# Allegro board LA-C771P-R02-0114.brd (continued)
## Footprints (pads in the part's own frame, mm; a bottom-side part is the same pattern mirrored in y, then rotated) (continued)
W25Q64DWSSIG_SO8
  oval 0.635x1.676 smd: 1(0,0) 2(1.27,0) 3(2.54,0) 4(3.81,0) 5(3.81,7.25) 6(2.54,7.25) 7(1.27,7.25) 8(0,7.25)
Y_7V25000014_4P
  rect 1.397x1.194 smd: 1(0,0) 2(2.2,0) 3(2.2,1.7) 4(0,1.7)
Y_CRG3201212_4P
  rect 1.397x1.194 smd: 1(0,0) 2(2.2,0) 3(2.2,1.6) 4(0,1.6)
Y_Q13FC135000040_2P
  rect 0.991x1.803 smd: 1(0,0) 2(2.5,0)
Y_X3G025000DC1H_4P
  rect 1.397x1.194 smd: 1(0,0) 2(2.2,0) 3(2.2,1.7) 4(0,1.7)
YSLC05CH_SOT23-3
  oval 1.016x1.524 smd: 1(0,0) 2(0.965,2.083) 3(-0.965,2.083)
Z32H320TC-LPC-T28-233_TSSOP28
  oval 0.381x1.626 smd: 1(0,0) 2(0.65,0) 3(1.3,0) 4(1.95,0) 5(2.6,0) 6(3.25,0) 7(3.9,0) 8(4.55,0) 9(5.2,0) 10(5.85,0) 11(6.5,0) 12(7.15,0) 13(7.8,0) 14(8.45,0) 15(8.45,5.8) 16(7.8,5.8) 17(7.15,5.8) 18(6.5,5.8) 19(5.85,5.8) 20(5.2,5.8) 21(4.55,5.8) 22(3.9,5.8) 23(3.25,5.8) 24(2.6,5.8) 25(1.95,5.8) 26(1.3,5.8) 27(0.65,5.8) 28(0,5.8)

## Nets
1.05VS_GATE: CQ20.1 Q5.1 RQ9.1 UQ3.4
1.8VS_ON: CQ12.2 RQ3.1 UQ2.3
1.35VS_ON: CQ15.2 RQ4.1 UQ2.5
3V5V_EN: PC313.1 PR306.2 PR307.2 PR308.1 PU301.1 PU302.1
3V/5VALW_PG: PR314.2 PR501.2 PR601.1 PU301.2 UB1.15
3V_FB: PC302.1 PU301.3
3V_SN: PC312.1 PR305.2
3V_VIN: PC301.1 PC303.1 PC305.1 PC306.1 PL301.2 PU301.8
3VS_ON: CQ4.1 RQ1.1 UQ1.3
5V_FB: PC317.1 PU302.3
5V_SN: PC326.1 PR311.2
5V_VIN: PC314.1 PC315.1 PC316.1 PC319.1 PL303.2 PR312.1 PU302.8
5VS_ON: CQ7.2 RQ2.2 UQ1.5
+0.675VS: CD16.1 CD17.1 CD18.1 JDIMM1.203 JDIMM1.204 PJ403.2 RQ6.1
+0.675VS_R: Q3.1 RQ6.2
+0.675VSP: PC406.1 PC407.1 PJ403.1 PU303.2 PU303.20
+1.05VALW: CC50.2 CC51.2 CC52.2 CC53.2 CC55.2 CC93.1 CQ17.2 PJ501.2 PR123.1 UC4.B6 UC4.C3 UC4.C5 UC4.U22 UC4.V18 UC4.V22 UC4.Y19 UQ3.5 UQ3.6 UQ3.7 UQ3.8
+1.05VALWP: PC503.1 PC504.1 PC505.1 PC506.1 PC507.1 PJ501.1 PL403.2 PR505.1
+1.05VS: CC54.1 CC56.1 CC57.1 CC58.1 CC59.2 CC60.2 CC62.2 CC63.2 CC64.2 CC65.2 CC66.2 CC68.2 CC72.2 CC73.2 CC75.2 CC76.2 CC77.2 CC78.2 CC80.2 CC82.2 CC84.2 CC85.2 CC86.2 CC87.2 CC88.2 CC90.2 CC92.2 CQ18.2 CQ19.2 PR122.1 RB23.2 RC20.2 RC39.1 RC74.1 RC75.2 RQ7.2 UC4.AA33 UC4.AA36 UC4.AD35 UC4.AF16 UC4.AF18 UC4.AF21 UC4.AF33 UC4.AF35 UC4.AF36 UC4.AG21 UC4.AG33 UC4.AG35 UC4.AJ18 UC4.AJ36 UC4.AK18 UC4.AK19 UC4.AK21 UC4.AK35 UC4.AK36 UC4.AM16 UC4.AM18 UC4.AM21 UC4.AN18 UC4.AN19 UC4.AN21 UC4.AN25 UC4.AN29 UC4.AN30 UC4.G1 UC4.M14 UC4.U18 UC4.U19 UC4.U33 UC4.U35 UC4.V24 UC4.V32 UC4.V33 UC4.Y18 UC4.Y22 UC4.Y24 UC4.Y35 UC4.Y36 UQ3.1 UQ3.2 UQ3.3
+1.05VS_R: Q4.1 RQ7.1
+1.05VS_SOC: RC75.1 UC4.AC32 UC4.Y32
+1.05VSP_ON: PC501.1 PR501.1 PR503.1 PU501.7
+1.8VALW: CC22.1 CC61.1 CQ9.2 CW4.1 PJ602.2 QC2.2 QC3.2 RB7.2 RB13.1 RC26.1 RC28.2 RC29.2 RC35.1 RC36.2 RC38.1 RC45.1 RC46.1 RC50.1 RC51.1 RC52.1 RC59.1 RC61.1 RC81.2 RM19.2 RPC5.5 RPC5.6 RPC5.7 RPC5.8 RPC6.3 RPC6.4 RW5.1 RW8.1 UC4.AA18 UC4.N20 UC4.U24 UC4.U25 UC4.V25 UC10.8 UQ2.1 UQ2.2 UW2.1
+1.8VALWP: PC604.1 PC605.1 PJ602.1 PR603.1 PU601.3 PU601.4
+1.8VS: CC67.1 CC69.1 CC70.1 CC71.1 CC74.1 CY12.1 PJ5.2 QC4.2 QC5.2 QY2.2 QY3.2 RA2.2 RA5.2 RC9.2 RC14.1 RC17.1 RC21.1 RC22.1 RC58.1 RC79.2 RC82.2 RPC3.5 RPC3.6 RPC3.7 RPC3.8 RPC9.5 RPC9.6 RPC9.7 RPY1.3 RPY1.4 RX3.1 RY2.1 UC4.AM30 UC4.AM32 UC4.AN32 UC4.U38 UC5.5 UC6.5 UC7.5 UC8.5
+1.8VS_AVDD2: CA9.1 RA5.1 UA1.40
+1.8VS_OUT: CQ11.2 PJ5.1 UQ2.13 UQ2.14
+1.35V: CC31.2 CC32.2 CD4.1 CD5.1 CD6.1 CD7.1 CD8.1 CD9.1 CD10.1 CD11.1 CD12.1 CD13.1 CD14.1 CD15.1 CQ16.2 JDIMM1.75 JDIMM1.76 JDIMM1.81 JDIMM1.82 JDIMM1.87 JDIMM1.88 JDIMM1.93 JDIMM1.94 JDIMM1.99 JDIMM1.100 JDIMM1.105 JDIMM1.106 JDIMM1.111 JDIMM1.112 JDIMM1.117 JDIMM1.118 JDIMM1.123 JDIMM1.124 PJ1.2 PJ2.2 PJ401.2 PJ402.2 RC6.1 RD1.1 RD3.1 UQ2.6 UQ2.7
+1.35V_SOC: CC33.2 CC34.2 CC35.2 CC36.2 CC37.1 CC38.1 PJ1.1 PJ2.1 RC69.2 UC4.A48 UC4.AK38 UC4.AM38 UC4.AV41 UC4.AV42 UC4.BB46 UC4.BD49 UC4.BD52 UC4.BD53 UC4.BF44 UC4.BG51 UC4.BJ48 UC4.C51 UC4.D44 UC4.F49 UC4.F52 UC4.F53 UC4.H46 UC4.M41 UC4.M42 UC4.V38 UC4.Y38
+1.35VP: PC409.1 PC410.1 PC411.1 PC412.1 PC413.1 PC414.1 PJ401.1 PJ402.1 PL402.1 PR406.1 PR407.2 PU303.5 PU303.19
+1.35VS: CC40.1 CC41.1 CC42.1 CC43.1 CC44.1 CC45.1 CC46.1 CC47.1 CC48.1 CC49.1 PJ6.2 RC43.1 RC70.2 UC4.AA25 UC4.AD36 UC4.AF19 UC4.AG18 UC4.AG19 UC4.AG32 UC4.AJ19 UC4.U36 UC4.V36
+1.35VS_OUT: CQ13.2 PJ6.1 UQ2.8 UQ2.9
+3V_HDD: CO13.1 JHDD1.8 JHDD1.9 JHDD1.10 RO2.2
+3V_HUB: CS9.1 RS12.1 RS13.1 RS14.1 US2.20
+3V_LAN: CL7.1 CL8.1 CL9.1 CL10.1 RL1.2 RL4.2 UL1.11 UL1.23 UL1.32
+3VALW: C2.1 C12.1 CL1.2 CQ1.2 D3.3 JP1.1 JPWRB1.5 PJ301.2 PJ502.1 PJ601.1 PR105.2 PR502.1 PR712.1 PR729.2 RB2.1 RB27.1 RC27.2 RC76.2 RL1.1 UC9.5 UQ1.1 UQ1.2
+3VALW_EC: CB3.1 CB4.1 CB5.1 CB6.1 L3.1 RB2.2 RB4.2 RB5.2 RB10.2 RB18.1 RB20.2 RB21.2 RPB1.1 RPB1.2 RW3.1 UB1.22 UB1.33 UB1.96
+3VALW_SOC: CC79.1 CC81.1 CC83.1 RC76.1 UC4.N18 UC4.N22 UC4.P18
+3VALWP: PC307.1 PC308.1 PC309.1 PC310.1 PJ301.1 PL302.2 PR302.2 PU301.4
+3VDD_CODEC: CA1.1 CA2.1 CA18.2 RA1.2 UA1.1 UA1.36
+3VLP: CB7.1 PC311.1 PR107.2 PR115.2 PR222.2 PR314.1 PU301.5 R3.2 R7.2 R16.2 RB4.1 RB6.2 RB11.1 UA1.20 UB1.111
+3VS: CD19.1 CR5.2 CR6.2 CX2.1 CX10.2 JDIMM1.199 JEDP1.16 PJ3.2 PR602.1 QX2.3 QY1.5 R1.1 RA1.1 RA15.2 RB14.2 RB15.2 RC25.1 RC68.2 RC77.2 RC78.2 RL2.1 RM1.1 RO2.1 RPB1.3 RPB1.4 RPC1.2 RPC1.3 RPC1.4 RR8.2 RW1.2 RW4.1 UR1.9 UX1.5
+3VS_1.8VS_SOC: RC78.1 RC79.1 UC4.AM27
+3VS_CMOS: CX12.1 JEDP1.1 RX10.2
+3VS_OUT: CQ3.2 PJ3.1 UQ1.13 UQ1.14
+3VS_R_CMOS: CX11.1 QX2.1 RX10.1
+3VS_SOC: CC89.1 CC91.1 RC77.1 UC4.AN24 UC4.AN27
+3VS_TCM: CW1.1 CW2.1 CW3.1 RW1.1 UW1.10 UW1.19 UW1.24 UW1.28
+3VS_WLAN: CM1.1 JWLAN1.2 JWLAN1.24 JWLAN1.39 JWLAN1.41 JWLAN1.52 RM1.2 RM18.2 RM20.2
+5V_HUB: CS7.1 CS8.1 RS10.1 RS15.2 US2.19
+5V_ODD: CO9.1 JODD1.9 JODD1.10 RO1.2
+5VALW: CQ8.2 CS3.2 CS10.1 CS13.2 PC601.1 PJ302.2 PR404.1 PR405.1 PR718.2 PR719.1 PR722.1 PU601.6 RQ5.2 RQ9.2 RS15.1 UQ1.4 UQ1.6 UQ1.7 UQ2.4 US1.5 US3.5
+5VALWP: PC321.1 PC322.1 PC323.1 PC324.1 PJ302.1 PL304.2 PR309.2 PU302.4
+5VDDA_CODEC: CA7.1 CA8.1 RA4.1 UA1.26
+5VS: CO10.1 CO11.1 CO12.1 PJ4.2 R2.1 R14.2 RA3.1 RA4.2 RB8.2 RB9.2 RB12.2 RO1.1 RO4.1 UY1.1
+5VS_HDD: CO14.1 JHDD1.14 JHDD1.15 JHDD1.16 RO4.2
+5VS_OUT: CQ5.2 PJ4.1 UQ1.8 UQ1.9
+5VS_PVDD: CA4.2 CA5.1 CA6.1 RA3.2 UA1.41 UA1.46
+12.6VB_DDR: PC401.1 PC402.1 PC403.1 PC404.1 PL401.2 PQ401.5 PR408.1
+AV12: CR1.1 CR2.1 UR1.7
+DV12S: CR3.1 CR4.1 UR1.11
+DV33_18: CR10.2 UR1.15
+V18R: CB11.1 UB1.124
+VCC_LPC: CB14.2 RB11.2 RB13.2 UB1.9
+VCC_SPI: CB13.2 RB6.1 RB7.1 UB1.125
GND: C1.2 C2.2 C3.2 C4.2 C5.2 C6.2 C9.2 C10.2 C11.2 C12.2 CA1.2 CA2.2 CA3.2 CA4.1 CA5.2 CA6.2 CA10.2 CA12.1 CA18.1 CA22.1 CA28.2 CA29.2 CB3.2 CB4.2 CB5.2 CB6.2 CB7.2 CB8.2 CB10.1 CB11.2 CB12.2 CB13.1 CB14.1 CC1.2 CC2.1 CC3.1 CC4.1 CC5.1 CC12.2 CC13.2 CC14.2 CC15.2 CC16.2 CC17.2 CC18.2 CC19.2 CC20.2 CC21.2 CC22.2 CC23.2 CC24.2 CC25.2 CC26.1 CC27.2 CC28.2 CC29.2 CC30.2 CC33.1 CC34.1 CC35.1 CC36.1 CC37.2 CC38.2 CC39.2 CC40.2 CC41.2 CC42.2 CC43.2 CC44.2 CC45.2 CC46.2 CC47.2 CC48.2 CC49.2 CC50.1 CC51.1 CC52.1 CC53.1 CC54.2 CC55.1 CC56.2 CC57.2 CC58.2 CC59.1 CC60.1 CC61.2 CC62.1 CC63.1 CC64.1 CC65.1 CC66.1 CC67.2 CC68.1 CC69.2 CC70.2 CC71.2 CC72.1 CC73.1 CC74.2 CC75.1 CC76.1 CC77.1 CC78.1 CC79.2 CC80.1 CC81.2 CC82.1 CC83.2 CC84.1 CC85.1 CC86.1 CC87.1 CC88.1 CC89.2 CC90.1 CC91.2 CC92.1 CC93.2 CC94.2 CC95.2 CD1.2 CD2.2 CD3.2 CD4.2 CD5.2 CD6.2 CD7.2 CD8.2 CD9.2 CD10.2 CD11.2 CD12.2 CD13.2 CD14.2 CD15.2 CD16.2 CD17.2 CD18.2 CD19.2 CL1.1 CL2.2 CL3.2 CL4.2 CL5.2 CL6.2 CL7.2 CL8.2 CL9.2 CL10.2 CL13.1 CL15.2 CL16.1 CLRP1.2 CLRP2.2 CM1.2 CO9.2 CO10.2 CO11.2 CO12.2 CO13.2 CO14.2 CQ1.1 CQ2.1 CQ3.1 CQ4.2 CQ5.1 CQ6.1 CQ7.1 CQ8.1 CQ9.1 CQ10.1 CQ11.1 CQ12.1 CQ13.1 CQ14.1 CQ15.1 CQ16.1 CQ17.1 CQ18.1 CQ19.1 CQ20.2 CR1.2 CR2.2 CR3.2 CR4.2 CR5.1 CR6.1 CR9.2 CR10.1 CR11.2 CR12.2 CS3.1 CS4.2 CS5.2 CS6.2 CS7.2 CS8.2 CS9.2 CS10.2 CS11.2 CS12.1 CS13.1 CS14.2 CW1.2 CW2.2 CW3.2 CW4.2 CX1.2 CX2.2 CX9.2 CX10.1 CX11.2 CX12.2 CX13.2 CX14.1 CX15.1 CY9.2 CY10.1 CY11.1 CY12.2 D1.1 D2.1 D3.1 D4.1 DA3.1 DA4.1 DA5.1 DL2.2 DS1.3 DS2.2 DS3.2 DY1.3 DY2.3 DY3.3 H1.1(TP-1) H2.1(TP-1) H3.1(TP-1) H4.1(TP-1) H5.1(TP-1) H6.1(TP-1) H7.1(TP-1) H8.1(TP-1) H9.1(TP-1) H10.1(TP-1) H11.1(TP-1) H12.1(TP-1) H13.1(TP-1) H14.1(TP-1) J1.1 J2.1 JBATT1.7 JBATT1.8 JBATT1.9 JBATT1.10 JBATT1.11 JBATT1.12 JDCIN1.3 JDCIN1.4 JDIMM1.2 JDIMM1.3 JDIMM1.8 JDIMM1.9 JDIMM1.13 JDIMM1.14 JDIMM1.19 JDIMM1.20 JDIMM1.25 JDIMM1.26 JDIMM1.31 JDIMM1.32 JDIMM1.37 JDIMM1.38 JDIMM1.43 JDIMM1.44 JDIMM1.48 JDIMM1.49 JDIMM1.54 JDIMM1.55 JDIMM1.60 JDIMM1.61 JDIMM1.65 JDIMM1.66 JDIMM1.71 JDIMM1.72 JDIMM1.127 JDIMM1.128 JDIMM1.133 JDIMM1.134 JDIMM1.138 JDIMM1.139 JDIMM1.144 JDIMM1.145 JDIMM1.150 JDIMM1.151 JDIMM1.155 JDIMM1.156 JDIMM1.161 JDIMM1.162 JDIMM1.167 JDIMM1.168 JDIMM1.172 JDIMM1.173 JDIMM1.178 JDIMM1.179 JDIMM1.184 JDIMM1.185 JDIMM1.189 JDIMM1.190 JDIMM1.195 JDIMM1.196 JDIMM1.205 JDIMM1.206 JEDP1.5 JEDP1.6 JEDP1.11 JEDP1.14 JEDP1.17 JEDP1.23 JEDP1.31 JEDP1.32 JHDD1.1 JHDD1.4 JHDD1.7 JHDD1.11 JHDD1.12 JHDD1.13 JHDD1.17 JHDD1.19 JHDD1.23 JHDD1.24 JHDMI1.2 JHDMI1.5 JHDMI1.8 JHDMI1.11 JHDMI1.17 JHDMI1.20 JHDMI1.21 JHDMI1.22 JHDMI1.23 JKB1.31 JKB1.32 JKB2.31 JKB2.32 JODD1.1 JODD1.4 JODD1.7 JODD1.12 JODD1.13 JODD1.14 JODD1.15 JP1.4 JPWRB1.1 JPWRB1.2 JPWRB1.7 JPWRB1.8 JRTC1.2 JSB1.5 JSB1.6 JSB1.7 JSB1.8 JSD1.3 JSD1.6 JSD1.12 JSD1.13 JSPK1.3 JSPK1.4 JTP1.4 JTP1.7 JTP1.8 JUSB1.4 JUSB1.7 JUSB1.10 JUSB1.11 JUSB1.12 JUSB1.13 JUSB2.4 JUSB2.5 JUSB2.6 JUSB2.7 JUSB2.8 JWLAN1.4 JWLAN1.9 JWLAN1.15 JWLAN1.18 JWLAN1.21 JWLAN1.26 JWLAN1.27 JWLAN1.29 JWLAN1.34 JWLAN1.35 JWLAN1.37 JWLAN1.40 JWLAN1.43 JWLAN1.50 L1.2 L2.2 L4.1 PC100.2 PC101.2 PC102.2 PC103.2 PC104.2 PC105.2 PC203.2 PC204.2 PC205.2 PC206.2 PC207.1 PC209.2 PC210.2 PC211.1 PC212.2 PC213.2 PC215.1 PC216.1 PC217.1 PC218.2 PC219.2 PC220.2 PC222.2 PC223.2 PC301.2 PC303.2 PC305.2 PC306.2 PC307.2 PC308.2 PC309.2 PC310.2 PC311.2 PC312.2 PC313.2 PC314.2 PC315.2 PC316.2 PC319.2 PC320.2 PC321.2 PC322.2 PC323.2 PC324.2 PC325.2 PC326.2 PC327.2 PC401.2 PC402.2 PC403.2 PC404.2 PC406.2 PC407.2 PC408.1 PC409.2 PC410.2 PC411.2 PC412.2 PC413.2 PC414.2 PC415.2 PC416.2 PC417.2 PC418.2 PC419.2 PC501.2 PC502.2 PC504.2 PC505.2 PC506.2 PC507.2 PC508.2 PC601.2 PC602.2 PC603.2 PC605.2 PC701.2 PC702.1 PC703.1 PC704.1 PC705.2 PC706.1 PC707.1 PC708.1 PC709.1 PC710.1 PC711.1 PC712.1 PC715.1 PC717.1 PC718.1 PC720.2 PC721.2 PC722.2 PC723.1 PC724.2 PC731.2 PC732.1 PC733.1 PC734.1 PC735.1 PC736.1 PC738.2 PC739.2 PC740.2 PC741.2 PC742.1 PC743.1 PC744.2 PC745.1 PC746.1 PC747.1 PC748.1 PC749.1 PC750.2 PC752.1 PC755.2 PC762.1 PC763.1 PC764.1 PC765.1 PC766.1 PC767.1 PC768.1 PC769.1 PC770.1 PC771.1 PC772.1 PC773.1 PC774.1 PC775.1 PC776.1 PC777.1 PC778.1 PC779.1 PC780.1 PC781.1 PC782.2 PC783.1 PC784.1 PC785.2 PC786.2 PC787.2 PH703.1 PH704.2 PQ205.1 PQ205.2 PQ205.3 PQ402.1 PQ402.2 PQ402.3 PQ701.5 PQ701.6 PQ701.7 PQ702.5 PQ702.6 PQ702.7 PR200.1 PR216.2 PR225.2 PR229.2 PR303.2 PR308.2 PR313.2 PR409.2 PR503.2 PR506.2 PR604.2 PR605.2 PR707.2 PR715.1 PR727.2 PR732.1 PU1.22 PU1.29 PU301.9 PU302.9 PU303.1 PU303.3 PU303.14 PU303.21 PU501.4 PU501.8 PU501.9 PU601.1 PU602.33 Q2.3 Q3.3 Q4.3 Q5.3 QB1.3 QC1.3 QM1.1 QM1.4 QX1.3 QY1.1 QY1.4 RA10.1 RA21.1 RA24.1 RA26.1 RA28.1 RA31.2 RB25.1 RB31.1 RB32.2 RC1.1 RC2.1 RC3.1 RC4.1 RC5.1 RC7.1 RC15.2 RC19.2 RC30.1 RC31.1 RC32.1 RC33.1 RC34.1 RC37.2 RC44.1 RC55.2 RC56.1 RC57.1 RC60.1 RC62.1 RC63.2 RC64.1 RC65.1 RC73.2 RD2.1 RD4.1 RD5.1 RD6.1 RL3.2 RL5.1 RL6.1 RL7.1 RM13.1 RO5.1 RPC2.1 RPC2.2 RPC2.3 RPC6.1 RPC6.2 RQ8.2 RR1.1 RS11.2 RX4.2 RX5.2 RX8.1 RY10.2 SW3.3 SW3.4 SW3.5 SW3.6 SW4.3 SW4.4 SW4.5 SW4.6 SW5.2 SW5.4 SW5.5 UA1.49 UB1.11 UB1.24 UB1.35 UB1.94 UB1.113 UC4.A3 UC4.A5 UC4.A6 UC4.A11 UC4.A15 UC4.A19 UC4.A23 UC4.A27 UC4.A31 UC4.A35 UC4.A39 UC4.A43 UC4.A47 UC4.A49 UC4.A51 UC4.A52 UC4.AA1 UC4.AA3 UC4.AA16 UC4.AA19 UC4.AA21 UC4.AA32 UC4.AA35 UC4.AA38 UC4.AA53 UC4.AB4 UC4.AB6 UC4.AB10 UC4.AB41 UC4.AB45 UC4.AB47 UC4.AB48 UC4.AB50 UC4.AB51 UC4.AC16 UC4.AC18 UC4.AC19 UC4.AC21 UC4.AC25 UC4.AC33 UC4.AC35 UC4.AC36 UC4.AC38 UC4.AD7 UC4.AD16 UC4.AD18 UC4.AD19 UC4.AD21 UC4.AD25 UC4.AD32 UC4.AD33 UC4.AD47 UC4.AE1 UC4.AE3 UC4.AE4 UC4.AE6 UC4.AE8 UC4.AE9 UC4.AE11 UC4.AE12 UC4.AE14 UC4.AE40 UC4.AE42 UC4.AE43 UC4.AE45 UC4.AE46 UC4.AE48 UC4.AE50 UC4.AE51 UC4.AE53 UC4.AF10 UC4.AF12 UC4.AF25 UC4.AF32 UC4.AF47 UC4.AG16 UC4.AG25 UC4.AG36 UC4.AG38 UC4.AH2 UC4.AH3 UC4.AH4 UC4.AH6 UC4.AH7 UC4.AH9 UC4.AH41 UC4.AH45 UC4.AH47 UC4.AH48 UC4.AH50 UC4.AH51 UC4.AJ1 UC4.AJ3 UC4.AJ16 UC4.AJ21 UC4.AJ25 UC4.AJ27 UC4.AJ29 UC4.AJ30 UC4.AJ32 UC4.AJ33 UC4.AJ35 UC4.AJ38 UC4.AJ53 UC4.AK10 UC4.AK14 UC4.AK16 UC4.AK33 UC4.AK41 UC4.AK44 UC4.AM2 UC4.AM3 UC4.AM7 UC4.AM12 UC4.AM19 UC4.AM24 UC4.AM25 UC4.AM29 UC4.AM33 UC4.AM35 UC4.AM36 UC4.AM40 UC4.AM44 UC4.AM51 UC4.AN1 UC4.AN3 UC4.AN5 UC4.AN6 UC4.AN8 UC4.AN9 UC4.AN11 UC4.AN12 UC4.AN14 UC4.AN16 UC4.AN22 UC4.AN33 UC4.AN35 UC4.AN36 UC4.AN38 UC4.AN40 UC4.AN42 UC4.AN43 UC4.AN45 UC4.AN46 UC4.AN48 UC4.AN49 UC4.AN51 UC4.AN53 UC4.AP40 UC4.AT4 UC4.AT12 UC4.AT16 UC4.AT19 UC4.AT24 UC4.AT27 UC4.AT30 UC4.AT35 UC4.AT38 UC4.AT47 UC4.AT52 UC4.AU1 UC4.AU3 UC4.AU24 UC4.AU30 UC4.AU38 UC4.AU51 UC4.AV7 UC4.AV12 UC4.AV13 UC4.AV14 UC4.AV18 UC4.AV19 UC4.AV24 UC4.AV27 UC4.AV30 UC4.AV35 UC4.AV38 UC4.AV47 UC4.AV51 UC4.AW3 UC4.AW13 UC4.AW19 UC4.AW27 UC4.AW35 UC4.AY4 UC4.AY9 UC4.AY10 UC4.AY22 UC4.AY32 UC4.AY36 UC4.AY50 UC4.B2 UC4.B52 UC4.B53 UC4.BA14 UC4.BA19 UC4.BA22 UC4.BA27 UC4.BA32 UC4.BA35 UC4.BA40 UC4.BA53 UC4.BB5 UC4.BB7 UC4.BB10 UC4.BB19 UC4.BB27 UC4.BB35 UC4.BC1 UC4.BC2 UC4.BC10 UC4.BC20 UC4.BC22 UC4.BC26 UC4.BC28 UC4.BC32 UC4.BC34 UC4.BC42 UC4.BD19 UC4.BD24 UC4.BD27 UC4.BD30 UC4.BD35 UC4.BE1 UC4.BE2 UC4.BE8 UC4.BE19 UC4.BE35 UC4.BE53 UC4.BF4 UC4.BF12 UC4.BF16 UC4.BF24 UC4.BF30 UC4.BF36 UC4.BF38 UC4.BG1 UC4.BG31 UC4.BG34 UC4.BG39 UC4.BG42 UC4.BG45 UC4.BG49 UC4.BG53 UC4.BH1 UC4.BH2 UC4.BH52 UC4.BH53 UC4.BJ2 UC4.BJ3 UC4.BJ5 UC4.BJ7 UC4.BJ11 UC4.BJ15 UC4.BJ19 UC4.BJ23 UC4.BJ27 UC4.BJ31 UC4.BJ35 UC4.BJ39 UC4.BJ43 UC4.BJ47 UC4.BJ49 UC4.BJ51 UC4.BJ52 UC4.C1 UC4.C14 UC4.C31 UC4.C34 UC4.C39 UC4.C42 UC4.C45 UC4.C49 UC4.C53 UC4.D12 UC4.D16 UC4.D24 UC4.D30 UC4.D36 UC4.D38 UC4.E1 UC4.E8 UC4.E19 UC4.E35 UC4.E53 UC4.F2 UC4.F5 UC4.F7 UC4.F19 UC4.F24 UC4.F27 UC4.F30 UC4.F35 UC4.G10 UC4.G20 UC4.G22 UC4.G26 UC4.G28 UC4.G32 UC4.G34 UC4.G42 UC4.H19 UC4.H27 UC4.H35 UC4.J1 UC4.J16 UC4.J19 UC4.J22 UC4.J27 UC4.J32 UC4.J35 UC4.J40 UC4.J53 UC4.K4 UC4.K9 UC4.K14 UC4.K22 UC4.K32 UC4.K36 UC4.K50 UC4.L13 UC4.L19 UC4.L27 UC4.L35 UC4.M19 UC4.M26 UC4.M27 UC4.M28 UC4.M34 UC4.M35 UC4.M38 UC4.M47 UC4.M51 UC4.N1 UC4.N16 UC4.N38 UC4.N51 UC4.P4 UC4.P9 UC4.P13 UC4.P16 UC4.P19 UC4.P20 UC4.P24 UC4.P32 UC4.P35 UC4.P38 UC4.P47 UC4.P52 UC4.T40 UC4.U1 UC4.U3 UC4.U5 UC4.U6 UC4.U8 UC4.U9 UC4.U11 UC4.U12 UC4.U14 UC4.U16 UC4.U21 UC4.U30 UC4.U32 UC4.U40 UC4.U42 UC4.U43 UC4.U45 UC4.U46 UC4.U48 UC4.U49 UC4.U51 UC4.U53 UC4.V7 UC4.V12 UC4.V16 UC4.V19 UC4.V21 UC4.V35 UC4.V40 UC4.V44 UC4.V51 UC4.Y7 UC4.Y9 UC4.Y10 UC4.Y14 UC4.Y16 UC4.Y21 UC4.Y25 UC4.Y33 UC4.Y41 UC4.Y44 UC5.3 UC6.3 UC7.3 UC8.3 UC9.3 UC10.4 UL1.33 UQ1.11 UQ1.15 UQ2.11 UQ2.15 UR1.25 US1.2 US2.25 US3.2 UW1.4 UW1.7 UW1.11 UW1.15 UW1.18 UW1.25 UW2.2 UX1.2 UY1.2 YC1.2 YC1.4 YL1.2 YL1.4
GNDA: CA7.2 CA8.2 CA9.2 CA11.2 CA13.1 CA14.2 CA16.1 CA17.2 CA19.2 CA20.2 CA21.2 JHP1.2 MIC1.2 RA14.1 RA21.2 RA22.1 RA23.1 RA24.2 RA26.2 RA28.2 UA1.25 UA1.38
VCC_3.3V: PC320.1 PU302.5
VDD_DDR: PC416.1 PR402.1 PR404.2 PU303.11
VIN: PC102.1 PC103.1 PC200.1 PD1.3 PL100.2 PL101.2 PQ201.5 PR215.1
+CARD_3V3: CR11.1 CR12.1 JSD1.4 LR1.1
+CARD_3V3_R: LR1.2 UR1.10
+CHGRTC: PD100.2 PR115.1
+CHGRTC_R: JRTC1.1 PR116.2
+DDR_A_VREF_CA: CD3.1 JDIMM1.126 RD3.2 RD4.2
+DDR_A_VREF_DQ: CD1.1 JDIMM1.1 RD1.2 RD2.2
+DDR_SOC_VREF: CC1.1 RC6.2 RC7.2 UC4.AF44
+EC_VCCA: CB1.1 CB2.1 L3.2 PR110.1 UB1.67
+HDMI_5V_OUT: CY9.1 CY11.2 JHDMI1.18 RPY1.1 RPY1.2 UY1.3
+INVPWR_B+: CX9.1 JEDP1.26 JEDP1.28 JEDP1.30 RX9.1
+IOVDD_CODEC: CA3.1 RA2.1 UA1.9
+LAN_VDD: CL2.1 CL3.1 CL4.1 CL5.1 CL6.1 UL1.3 UL1.8 UL1.22 UL1.24 UL1.30
+LCDVDD: CX1.1 JEDP1.18 JEDP1.20 RX2.1 UX1.1
+LINE1-VREFO-L: RA25.1 RA29.1 UA1.31
+LINE1-VREFO-R: RA27.2 UA1.30
+MIC2-VREFO: RA6.1 RA7.1 UA1.29
+RTCVCC: CC23.1 PD100.1 RC47.1 RC49.1 UC4.P22
+SOC_VCC: PC764.2 PC765.2 PC766.2 PC767.2 PC768.2 PC769.2 PC770.2 PC771.2 PC772.2 PC773.2 PC774.2 PC775.2 PC776.2 PC777.2 PC778.2 PC779.2 PC780.2 PC781.2 PC782.1 PC783.2 PC784.2 PC787.1 PL703.4 RC72.1 UC4.AA27 UC4.AA29 UC4.AA30 UC4.AC27 UC4.AC29 UC4.AC30 UC4.AD27 UC4.AD29 UC4.AD30 UC4.AF27 UC4.AF29 UC4.AG27 UC4.AG29 UC4.AG30 UC4.P26 UC4.P27 UC4.U27 UC4.U29 UC4.V27 UC4.V29 UC4.V30 UC4.Y27 UC4.Y29 UC4.Y30
+SOC_VNN: PC702.2 PC703.2 PC704.2 PC706.2 PC707.2 PC708.2 PC710.2 PC711.2 PC712.2 PC715.2 PC717.2 PC718.2 PC723.2 PC732.2 PC734.2 PC735.2 PC736.2 PC742.2 PC743.2 PC745.2 PC746.2 PC747.2 PC748.2 PC749.2 PC785.1 PC786.1 PL702.4 RC71.1 UC4.AA24 UC4.AC22 UC4.AC24 UC4.AD22 UC4.AD24 UC4.AF22 UC4.AF24 UC4.AG22 UC4.AG24 UC4.AJ22 UC4.AJ24 UC4.AK22 UC4.AK24 UC4.AK25 UC4.AK27 UC4.AK29 UC4.AK30 UC4.AK32 UC4.AM22
+USB3_VCCA: CS4.1 CS5.1 DS2.5 DS3.5 JUSB1.1 JUSB2.1 US1.1
+USB_SB: CS6.1 CS14.1 JSB1.1 JSB1.2 US3.1
ACDRV: PR209.2 PU1.4
ACN: PC208.2 PC209.1 PC210.1 PR202.3 PU1.1
ACP: PC207.2 PC208.1 PR202.2 PU1.2
ADP_I: PC215.2 PR112.2 PU1.7 UB1.65
APDIN: JDCIN1.1 JDCIN1.2 PF100.1
APDIN1: PC100.1 PC101.1 PF100.2 PL100.1 PL101.1
B+: PL200.1 PL301.1 PL303.1 PL401.1 PL701.2 PQ203.5 PQ203.6 PQ203.7 PQ203.8 PR202.4 PR301.2 RX9.2
BA+: PC201.2 PD1.2 PL201.2 PQ203.1 PQ203.2 PQ203.3 PR213.1 PR221.1
BATDRV: PR212.2 PU1.18
BATSRC: PR213.2 PU1.17
BATT+: PC105.1 PC218.1 PC220.1 PL102.2 PL103.2 PR221.4
BATT_CHG_LED#: R15.1 UB1.90
BATT_LOW_LED#: LED2.1 UB1.93
BEEP#: CA30.1 UB1.23
BKOFF#: RC8.2 RPC1.5 RX6.1
BOOT1: PR730.2 PU602.16
BOOTG: PR709.2 PU602.26
BQ24780VDD: PC213.1 PR228.1 PU1.24
BST_3V: PR304.1 PU301.6
BST_5V: PR310.1 PU302.6
BST_CHG: PR220.1 PU1.25
BST_DDR: PR401.2 PU303.18
BST_DDR_R: PC405.1 PR401.1
BT_OFF#: QM1.2 RC80.1 RM19.1
BT_OFF#_R: RC80.2 UC4.K2
CAPS_LED#: LED4.1 UB1.91
CARD_CLKREQ#: RPC3.4 UC4.BD7 UR1.24
CLK_PCIE_CARD: UC4.AF7 UR1.3
CLK_PCIE_CARD#: UC4.AF9 UR1.4
CLK_PCIE_LAN: UC4.AK6 UL1.15
CLK_PCIE_LAN#: UC4.AK4 UL1.16
CLK_PCIE_WLAN: JWLAN1.13 UC4.AM6
CLK_PCIE_WLAN#: JWLAN1.11 UC4.AM4
CLR_CMOS#: QB1.1 RC83.2 RC84.2
CMOS_ON#: RX11.1 UB1.86
CMSRC: PR211.2 PU1.3
CPU_B+: PC701.1 PC720.1 PC721.1 PC722.1 PC739.1 PC740.1 PC741.1 PL701.1 PQ701.2 PQ701.3 PQ701.4 PQ701.10 PQ702.2 PQ702.3 PQ702.4 PQ702.10
CPVEE: CA22.2 UA1.34
CS_DDR: PR402.2 PU303.13
DBG_UART_RXD: T15.1(TP-1) UC4.BC16
DBG_UART_TXD: T14.1(TP-1) UC4.BD14
DCHG_I: PC216.2 PU1.8
DDI0_RCOMPN: RC11.1 UC4.AK13
DDI0_RCOMPP: RC11.2 UC4.AK12
DDI1_ENABLE: RC9.1 UC4.P30
DDI1_ENBKL: CC2.2 RC10.1 RPC2.8 UC4.J30 UC5.2
DDI1_ENVDD: CC3.2 RC13.1 RPC2.7 UC4.N30 UC6.2
DDI1_PWM: CC4.2 RPC2.6 UC4.M30 UC7.2
DDR_A_BS0: JDIMM1.109 UC4.K47
DDR_A_BS1: JDIMM1.108 UC4.K44
DDR_A_BS2: JDIMM1.79 UC4.D52
DDR_A_CAS#: JDIMM1.115 UC4.M44
DDR_A_CKE0: JDIMM1.73 UC4.C47
DDR_A_CKE2: JDIMM1.74 UC4.F44
DDR_A_CLK0: JDIMM1.101 UC4.M50
DDR_A_CLK0#: JDIMM1.103 UC4.M48
DDR_A_CLK2: JDIMM1.102 UC4.P50
DDR_A_CLK2#: JDIMM1.104 UC4.P48
DDR_A_CS0#: JDIMM1.114 UC4.P44
DDR_A_CS2#: JDIMM1.121 UC4.P45
DDR_A_D0: JDIMM1.5 UC4.M36
DDR_A_D1: JDIMM1.7 UC4.J36
DDR_A_D2: JDIMM1.15 UC4.P40
DDR_A_D3: JDIMM1.17 UC4.M40
DDR_A_D4: JDIMM1.4 UC4.P36
DDR_A_D5: JDIMM1.6 UC4.N36
DDR_A_D6: JDIMM1.16 UC4.K40
DDR_A_D7: JDIMM1.18 UC4.K42
DDR_A_D8: JDIMM1.21 UC4.B32
DDR_A_D9: JDIMM1.23 UC4.C32
DDR_A_D10: JDIMM1.33 UC4.C36
DDR_A_D11: JDIMM1.35 UC4.A37
DDR_A_D12: JDIMM1.22 UC4.C33
DDR_A_D13: JDIMM1.24 UC4.A33
DDR_A_D14: JDIMM1.34 UC4.C37
DDR_A_D15: JDIMM1.36 UC4.B38
DDR_A_D16: JDIMM1.39 UC4.F36
DDR_A_D17: JDIMM1.41 UC4.G38
DDR_A_D18: JDIMM1.51 UC4.F42
DDR_A_D19: JDIMM1.53 UC4.J42
DDR_A_D20: JDIMM1.40 UC4.G40
DDR_A_D21: JDIMM1.42 UC4.C38
DDR_A_D22: JDIMM1.50 UC4.G44
DDR_A_D23: JDIMM1.52 UC4.D42
DDR_A_D24: JDIMM1.57 UC4.A41
DDR_A_D25: JDIMM1.59 UC4.C41
DDR_A_D26: JDIMM1.67 UC4.A45
DDR_A_D27: JDIMM1.69 UC4.B46
DDR_A_D28: JDIMM1.56 UC4.C40
DDR_A_D29: JDIMM1.58 UC4.B40
DDR_A_D30: JDIMM1.68 UC4.B48
DDR_A_D31: JDIMM1.70 UC4.B47
DDR_A_D32: JDIMM1.129 UC4.K52
DDR_A_D33: JDIMM1.131 UC4.K51
DDR_A_D34: JDIMM1.141 UC4.T52
DDR_A_D35: JDIMM1.143 UC4.T51
DDR_A_D36: JDIMM1.130 UC4.L51
DDR_A_D37: JDIMM1.132 UC4.L53
DDR_A_D38: JDIMM1.140 UC4.R51
DDR_A_D39: JDIMM1.142 UC4.R53
DDR_A_D40: JDIMM1.147 UC4.T47
DDR_A_D41: JDIMM1.149 UC4.T45
DDR_A_D42: JDIMM1.157 UC4.Y40
DDR_A_D43: JDIMM1.159 UC4.V41
DDR_A_D44: JDIMM1.146 UC4.T48
DDR_A_D45: JDIMM1.148 UC4.T50
DDR_A_D46: JDIMM1.158 UC4.Y42
DDR_A_D47: JDIMM1.160 UC4.AB40
DDR_A_D48: JDIMM1.163 UC4.V45
DDR_A_D49: JDIMM1.165 UC4.V47
DDR_A_D50: JDIMM1.175 UC4.AD48
DDR_A_D51: JDIMM1.177 UC4.AD50
DDR_A_D52: JDIMM1.164 UC4.V48
DDR_A_D53: JDIMM1.166 UC4.V50
DDR_A_D54: JDIMM1.174 UC4.AB44
DDR_A_D55: JDIMM1.176 UC4.Y45
DDR_A_D56: JDIMM1.181 UC4.V52
DDR_A_D57: JDIMM1.183 UC4.W51
DDR_A_D58: JDIMM1.191 UC4.AC53
DDR_A_D59: JDIMM1.193 UC4.AC51
DDR_A_D60: JDIMM1.180 UC4.W53
DDR_A_D61: JDIMM1.182 UC4.Y51
DDR_A_D62: JDIMM1.192 UC4.AD52
DDR_A_D63: JDIMM1.194 UC4.AD51
DDR_A_DM0: JDIMM1.11 UC4.G36
DDR_A_DM1: JDIMM1.28 UC4.B36
DDR_A_DM2: JDIMM1.46 UC4.F38
DDR_A_DM3: JDIMM1.63 UC4.B42
DDR_A_DM4: JDIMM1.136 UC4.P51
DDR_A_DM5: JDIMM1.153 UC4.V42
DDR_A_DM6: JDIMM1.170 UC4.Y50
DDR_A_DM7: JDIMM1.187 UC4.Y52
DDR_A_DQS0: JDIMM1.12 UC4.J38
DDR_A_DQS1: JDIMM1.29 UC4.C35
DDR_A_DQS2: JDIMM1.47 UC4.D40
DDR_A_DQS3: JDIMM1.64 UC4.B44
DDR_A_DQS4: JDIMM1.137 UC4.N53
DDR_A_DQS5: JDIMM1.154 UC4.T42
DDR_A_DQS6: JDIMM1.171 UC4.Y47
DDR_A_DQS7: JDIMM1.188 UC4.AB52
DDR_A_DQS#0: JDIMM1.10 UC4.K38
DDR_A_DQS#1: JDIMM1.27 UC4.B34
DDR_A_DQS#2: JDIMM1.45 UC4.F40
DDR_A_DQS#3: JDIMM1.62 UC4.C43
DDR_A_DQS#4: JDIMM1.135 UC4.M52
DDR_A_DQS#5: JDIMM1.152 UC4.T44
DDR_A_DQS#6: JDIMM1.169 UC4.Y48
DDR_A_DQS#7: JDIMM1.186 UC4.AA51
DDR_A_MA0: JDIMM1.98 UC4.K45
DDR_A_MA1: JDIMM1.97 UC4.H47
DDR_A_MA2: JDIMM1.96 UC4.L41
DDR_A_MA3: JDIMM1.95 UC4.H44
DDR_A_MA4: JDIMM1.92 UC4.H50
DDR_A_MA5: JDIMM1.91 UC4.G53
DDR_A_MA6: JDIMM1.90 UC4.H49
DDR_A_MA7: JDIMM1.86 UC4.D50
DDR_A_MA8: JDIMM1.89 UC4.G52
DDR_A_MA9: JDIMM1.85 UC4.E52
DDR_A_MA10: JDIMM1.107 UC4.K48
DDR_A_MA11: JDIMM1.84 UC4.E51
DDR_A_MA12: JDIMM1.83 UC4.F47
DDR_A_MA13: JDIMM1.119 UC4.J51
DDR_A_MA14: JDIMM1.80 UC4.B49
DDR_A_MA15: JDIMM1.78 UC4.B50
DDR_A_ODT0: JDIMM1.116 UC4.T41
DDR_A_ODT2: JDIMM1.120 UC4.P42
DDR_A_RAS#: JDIMM1.110 UC4.M45
DDR_A_RST#: CC20.1 CD2.1 JDIMM1.30 UC4.P41
DDR_A_WE#: JDIMM1.113 UC4.H51
DDR_CORE_PWROK: CC21.1 RC43.2 UC4.AB42 UC9.4
DDR_PWROK: CC94.1 PR406.2 PU303.10 UC4.AD42
DDR_RCOMP0: RC3.2 UC4.AD44
DDR_RCOMP1: RC4.2 UC4.AF45
DDR_RCOMP2: RC5.2 UC4.AD45
DDR_TERMN0: RC1.2 UC4.AF42
DDR_TERMN1: RC2.2 UC4.AH42
DEVSLP_SOC: T3.1(TP-1) UC4.AY14
DH_CHG: PR217.1 PU1.26
DISPOFF#: CX14.2 JEDP1.10 RX6.2 RX7.2 RX8.2
DL_CHG: PQ205.4 PU1.23
DRAM_VDD_S4_CLK: CC29.1 CC30.1 RC69.1 UC4.AD38 UC4.AF38
E51RXD_P80CLK: JP1.3 RM12.1 UB1.31
E51TXD_P80DATA: JP1.2 RM11.1 RM13.2 UB1.30
EC_BKOFF#: RX7.1 UB1.105
EC_CLEAR_CMOS: QB1.2 RB31.2 UB1.68
EC_CS0#: RPC8.8 UB1.128
EC_ENVDD: RX1.1 UB1.74
EC_KBRST#: RC36.1 UB1.2 UC4.B18
EC_LID_OUT#: RC35.2 UC4.C17
EC_MUTE#: RA10.2 RA12.1 RB12.1 UB1.83
EC_ON: PR306.1 UB1.112
EC_RSMRST#: CC16.1 RC37.1 UB1.100 UC4.B10
EC_RST#: CB8.1 RB10.1 UB1.37
EC_SCI#: RB18.2 RC17.2 UB1.20 UC4.BA12
EC_SCK: RPC8.5 UB1.126
EC_SDI: RPC8.6 UB1.120
EC_SDIO: RPC8.7 UB1.119
EC_SERIRQ: RB3.1 RW5.2 UC4.BG13 UW2.3
EC_SERIRQ_R: RB1.2 RB3.2 UB1.3
EC_SLP_S4#_R2: RB22.2 UB1.123
EC_SMB_CK1: PR104.2 PR219.1 RPB1.8 UB1.77
EC_SMB_CK1_1: PR219.2 PU1.12
EC_SMB_CK2: JDIMM1.202 QC4.1 RB16.2 RPB1.6
EC_SMB_DA1: PR102.2 PR218.1 RPB1.7 UB1.78
EC_SMB_DA1_1: PR218.2 PU1.11
EC_SMB_DA2: JDIMM1.200 QC5.1 RB17.2 RPB1.5
EC_SMB_R_CK2: RB16.1 UB1.79
EC_SMB_R_DA2: RB17.1 UB1.80
EC_SMCA: JBATT1.3 PR104.1
EC_SMDA: JBATT1.4 PR102.1
EC_WL_OFF#: RM5.2 UB1.72
ECAGND: CB1.2 CB2.2 L4.2 PH100.2 PR113.1 UB1.69
EDP_AUXN: CX3.1 UC4.AK2
EDP_AUXN_C: CX3.2 JEDP1.7 RX2.2
EDP_AUXP: CX4.1 UC4.AK3
EDP_AUXP_C: CX4.2 JEDP1.9 RX4.1
EDP_HPD#: CC5.2 QX1.1 RX3.2 UC4.K30
EDP_HPD_CONN: CX15.2 JEDP1.12 QX1.2 RX5.1
EDP_TXN0: CX6.1 UC4.AG1
EDP_TXN0_C: CX6.2 JEDP1.15
EDP_TXN1: CX8.1 UC4.AF2
EDP_TXN1_C: CX8.2 JEDP1.21
EDP_TXP0: CX5.1 UC4.AG3
EDP_TXP0_C: CX5.2 JEDP1.13
EDP_TXP1: CX7.1 UC4.AF3
EDP_TXP1_C: CX7.2 JEDP1.19
EN_0.675VSP: PC419.1 PR411.2 PU303.7
EN_DDR: PC418.1 PR410.2 PU303.8
ENLDO_3V5V: PR301.1 PR303.1 PU301.7
ENVDD: RC12.2 RPC1.6 RX1.2 UX1.4
EXT_MIC_RING2: RA6.2 RA18.1 UA1.17
EXT_MIC_SLEEVE: RA7.2 RA17.1 UA1.18
FB_1.05V: PC503.2 PR505.2 PR506.1 PU501.1
FB_DDR: PR407.1 PR409.1 PU303.6
GPIO_NC12: T2.1(TP-1) UC4.B30
GPIO_NC13: RC14.2 RC15.1 UC4.A29
GPIO_NC14: T1.1(TP-1) UC4.C29
GPIO_RCOMP: RC44.2 UC4.N26
GPIO_S0_SC_56: RC58.2 RC63.1 UC4.BC12
GPIO_S0_SC_63: RC21.2 UC4.BA30
GPIO_S0_SC_65: QC1.1 RC22.2 RC23.2 UC4.BC30
GPIO_S0_SC_92: T18.1(TP-1) UC4.BH30
GPIO_S0_SC_93: T19.1(TP-1) UC4.BG30
GPIO_S5_14: RPC5.3 UC4.J20
GPIO_S5_17: T8.1(TP-1) UC4.J24
H_PROCHOT#: CB12.1 RB24.2 RB26.2 RC20.1 UC4.C24
HDA_BIT_CLK: RPC4.6 UC4.BJ21
HDA_BITCLK_AUDIO: RA11.1 RPC4.3 UA1.6
HDA_RCOMP: RC19.1 UC4.BF20
HDA_RST#: RPC4.5 UC4.BG22
HDA_RST_AUDIO#: RPC4.4 UA1.11
HDA_SDIN0: RA13.2 UC4.BG19
HDA_SDIN0_AUDIO: RA13.1 UA1.8
HDA_SDOUT: RPC4.7 UC4.BG20
HDA_SDOUT_AUDIO: RPC4.2 UA1.5
HDA_SPKR: CA32.1 UC4.BH12
HDA_SYNC: RPC4.8 UC4.BH20
HDA_SYNC_AUDIO: RPC4.1 UA1.10
HDMI_C_CLK+: CY8.1 LY1.1 RY9.1 RY11.1
HDMI_C_CLK-: CY7.1 LY1.4 RY7.1 RY13.1
HDMI_C_TX0+: CY6.1 LY2.4 RY8.1 RY14.1
HDMI_C_TX0-: CY5.1 LY2.1 RY6.1 RY16.1
HDMI_C_TX1+: CY2.1 LY3.1 RY3.1 RY17.1
HDMI_C_TX1-: CY1.1 LY3.4 RY1.1 RY19.1
HDMI_C_TX2+: CY4.1 LY4.4 RY5.1 RY20.1
HDMI_C_TX2-: CY3.1 LY4.1 RY4.1 RY22.1
HDMI_CLK+: CY8.2 UC4.AP3
HDMI_CLK-: CY7.2 UC4.AP2
HDMI_DDCCLK: QY2.3 RPY1.6 UC4.C28
HDMI_DDCDATA: QY3.3 RPY1.5 UC4.C26
HDMI_GND: QY1.3 RY1.2 RY3.2 RY4.2 RY5.2 RY6.2 RY7.2 RY8.2 RY9.2
HDMI_HPD: CY10.2 DY1.4 DY1.7 JHDMI1.19 QY1.2 RY10.1
HDMI_HPD#: QY1.6 RY2.2 UC4.D27
HDMI_R_CK+: DY2.1 DY2.9 JHDMI1.10 LY1.2 RY11.2 RY12.2
HDMI_R_CK-: DY2.2 DY2.8 JHDMI1.12 LY1.3 RY12.1 RY13.2
HDMI_R_D0+: DY3.2 DY3.8 JHDMI1.7 LY2.3 RY14.2 RY15.2
HDMI_R_D0-: DY3.1 DY3.9 JHDMI1.9 LY2.2 RY15.1 RY16.2
HDMI_R_D1+: DY2.4 DY2.7 JHDMI1.4 LY3.2 RY17.2 RY18.2
HDMI_R_D1-: DY2.5 DY2.6 JHDMI1.6 LY3.3 RY18.1 RY19.2
HDMI_R_D2+: DY3.5 DY3.6 JHDMI1.1 LY4.3 RY20.2 RY21.2
HDMI_R_D2-: DY3.4 DY3.7 JHDMI1.3 LY4.2 RY21.1 RY22.2
HDMI_SCLK: DY1.2 DY1.8 JHDMI1.15 QY2.1 RPY1.8
HDMI_SDATA: DY1.1 DY1.9 JHDMI1.16 QY3.1 RPY1.7
HDMI_TX0+: CY6.2 UC4.AR3
HDMI_TX0-: CY5.2 UC4.AR1
HDMI_TX1+: CY2.2 UC4.AT2
HDMI_TX1-: CY1.2 UC4.AT3
HDMI_TX2+: CY4.2 UC4.AV3
HDMI_TX2-: CY3.2 UC4.AV2
HGNDA: CA14.1 DA3.3 JHP1.5 RA18.2
HGNDB: CA11.1 DA3.2 JHP1.7 RA17.2
HP_OUTL: CA23.1 RA19.1 RA25.2 UA1.32
HP_OUTR: CA24.1 RA20.1 RA29.2 UA1.33
HPOUT_L: CA17.1 RA8.1 RA19.2 RA22.2
HPOUT_L1: DA5.3 JHP1.4 RA8.2
HPOUT_R: CA19.1 RA9.1 RA20.2 RA23.2
HPOUT_R1: DA5.2 JHP1.1 RA9.2
HSIC_RCOMP: RC64.2 UC4.A7
HUB_BUSJ: RS13.2 US2.18
HUB_OVCJ: CS11.1 RS10.2 US2.1
HUB_VBUSM: CS12.2 RS14.2 US2.17
HUB_XIN: US2.4 YS1.1
HUB_XOUT: US2.3 YS1.3
HUB_XRSTJ: RS12.2 US2.16
ICLK_ICOMP: RC30.2 UC4.AD14
ICLK_RCOMP: RC31.2 UC4.AD13
ICLK_USB_TERMN: RC57.2 UC4.F10
ICLK_USB_TERMP: RC56.2 UC4.D10
ILB_RTC_EXTPAD: CC17.1 UC4.B8
ILB_RTC_X1: CC19.1 RC42.2 UC4.C9 YC2.2
ILB_RTC_X2: CC18.1 RC42.1 UC4.A9 YC2.1
INVT_PWM_SOC: JEDP1.8 RPC1.7 UC7.4
ISOLATE#: RL2.2 RL3.1 UL1.20
KSI0: JKB1.12 JKB2.12 UB1.55
KSI1: JKB1.1 JKB2.1 UB1.56
KSI2: JKB1.8 JKB2.8 UB1.57
KSI3: JKB1.9 JKB2.9 UB1.58
KSI4: JKB1.5 JKB2.5 UB1.59
KSI5: JKB1.6 JKB2.6 UB1.60
KSI6: JKB1.3 JKB2.3 UB1.61
KSI7: JKB1.2 JKB2.2 UB1.62
KSO0: JKB1.7 JKB2.7 UB1.39
KSO1: JKB1.11 JKB2.11 UB1.40
KSO2: JKB1.13 JKB2.13 UB1.41
KSO3: JKB1.18 JKB2.18 UB1.42
KSO4: JKB1.14 JKB2.14 UB1.43
KSO5: JKB1.10 JKB2.10 UB1.44
KSO6: JKB1.17 JKB2.17 UB1.45
KSO7: JKB1.15 JKB2.15 UB1.46
KSO8: JKB1.16 JKB2.16 UB1.47
KSO9: JKB1.4 JKB2.4 UB1.48
KSO10: JKB1.23 JKB2.23 UB1.49
KSO11: JKB1.22 JKB2.22 UB1.50
KSO12: JKB1.19 JKB2.19 UB1.51
KSO13: JKB1.20 JKB2.20 UB1.52
KSO14: JKB1.21 JKB2.21 UB1.53
KSO15: JKB1.24 JKB2.24 UB1.54
KSO16: JKB2.25 UB1.81
KSO17: JKB2.26 UB1.82
LAN_CLKREQ#: CC95.1 RPC3.1 UC4.BG5 UL1.12
LAN_MDIN0: DL2.1 TL1.7 UL1.2
LAN_MDIN1: DL2.6 TL1.1 UL1.5
LAN_MDIP0: DL2.3 TL1.8 UL1.1
LAN_MDIP1: DL2.4 TL1.2 UL1.4
LANGND: CL14.2 DL1.1 JLAN1.9 JLAN1.10 RL5.2 RL7.2
LDO1: CA16.2 RA14.2 UA1.27
LDO2: CA13.2 UA1.39
LDO3: CA12.2 UA1.7
LED1_GPIO: RL4.1 UL1.26
LG_DDR: PQ402.4 PU303.15
LGATE1: PQ702.8 PU602.19
LGATEG: PQ701.8 PU602.23
LID_SW#: C11.1 D2.3 JPWRB1.6 RB5.1 UB1.115
LINE1-L: CA23.2 UA1.22
LINE1-R: CA24.2 UA1.21
LINE2-L: CA25.2 RA32.1 UA1.24
LINE2-MIC: CA25.1 MIC1.1 RA27.1
LINE2-R: RA32.2 UA1.23
LPC_AD0: UB1.10 UC4.BH16 UW1.26
LPC_AD1: UB1.8 UC4.BJ17 UW1.23
LPC_AD2: UB1.7 UC4.BJ13 UW1.20
LPC_AD3: UB1.5 UC4.BG14 UW1.17
LPC_CLK_0: CC27.1 RC66.2 UC4.BG15
LPC_CLK_1: CC28.1 RC67.2 UC4.BH14
LPC_CLK_EC: RC66.1 UB1.12
LPC_CLK_TCM: RC67.1 RW2.2
LPC_CLKRUN#: RC68.1 RC82.1 UC4.BG16
LPC_FRAME#: UB1.4 UC4.BG17 UW1.22
LPC_RCOMP: RC65.2 UC4.BF18
LX_1.05V: PL403.1 PR504.1 PU501.6
LX_3V: PC304.2 PL302.1 PR305.1 PU301.10
LX_5V: PC318.2 PL304.1 PR311.1 PU302.10
LX_CHG: PC214.2 PL201.1 PQ204.1 PQ204.2 PQ204.3 PQ205.5 PR223.1 PU1.27
LX_DDR: PC405.2 PL402.2 PQ401.1 PQ401.2 PQ401.3 PQ402.5 PR403.1 PU303.16
ME_EN: QC1.2 RC23.1 UB1.99
NOVO#: D4.2 R16.1 SW5.1 SW5.3 UB1.34
NTC: PR723.1 PU602.7
NTC_1: PH704.1 PR723.2 PR727.1
NTCG: PR716.2 PU602.1
NTCG_1: PH703.2 PR715.2 PR716.1
NUVOTON_VTT: RB23.1 RB32.1 UB1.117
ODD_DETECT#_R: JODD1.8 RO5.2
ON/OFF#: C10.1 D2.2 J1.2 J2.2 JPWRB1.4 R3.1 UB1.114
P3: PQ202.5 PR202.1
PBTN_OUT#: RPC5.4 UB1.122 UC4.J26
PC_BEEP: CA31.2 UA1.12
PCH_USB3_RX0_N: LS2.4 RS9.2 UC4.E3
PCH_USB3_RX0_P: LS2.1 RS8.2 UC4.D4
PCH_USB3_TX0_N: CS2.2 UC4.K7
PCH_USB3_TX0_N_C: CS2.1 LS1.4 RS7.2
PCH_USB3_TX0_P: CS1.2 UC4.K6
PCH_USB3_TX0_P_C: CS1.1 LS1.1 RS6.2
PCIE_ATX_C_GRX_N0: CC9.2 UL1.14
PCIE_ATX_C_GRX_P0: CC8.2 UL1.13
PCIE_GTX_C_ARX_N0: CL12.2 UC4.AP10
PCIE_GTX_C_ARX_P0: CL11.2 UC4.AP12
PCIE_LAN_WAKE#: RB27.2 RM2.1 UB1.19 UL1.21
PCIE_PRX_DTX_N0_C: CL12.1 UL1.18
PCIE_PRX_DTX_N1: CR8.1 UC4.AT9
PCIE_PRX_DTX_N1_C: CR8.2 UR1.6
PCIE_PRX_DTX_N3: JWLAN1.23 UC4.AP7
PCIE_PRX_DTX_P0_C: CL11.1 UL1.17
PCIE_PRX_DTX_P1: CR7.1 UC4.AT10
PCIE_PRX_DTX_P1_C: CR7.2 UR1.5
PCIE_PRX_DTX_P3: JWLAN1.25 UC4.AP9
PCIE_PTX_C_DRX_N1: CC7.2 UR1.2
PCIE_PTX_C_DRX_N3: CC11.2 JWLAN1.31
PCIE_PTX_C_DRX_P1: CC6.2 UR1.1
PCIE_PTX_C_DRX_P3: CC10.2 JWLAN1.33
PCIE_PTX_DRX_N1: CC7.1 UC4.AV4
PCIE_PTX_DRX_N2: CC9.1 UC4.AT6
PCIE_PTX_DRX_N3: CC11.1 UC4.AP4
PCIE_PTX_DRX_P1: CC6.1 UC4.AV6
PCIE_PTX_DRX_P2: CC8.1 UC4.AT7
PCIE_PTX_DRX_P3: CC10.1 UC4.AP6
PCIE_RCOMPN: RC18.2 UC4.AP13
PCIE_RCOMPP: RC18.1 UC4.AP14
PCU_SMB_ALERT#: RPC9.2 UC4.BG11
PCU_SMB_CLK: QC4.3 RPC9.4 UC4.BH10
PCU_SMB_DATA: QC5.3 RPC9.3 UC4.BG12
PHASE1: PC751.1 PL703.1 PQ702.9 PR731.1 PU602.18
PHASEG: PC725.1 PL702.1 PQ701.9 PR713.1 PU602.24
PLT_RST_BUF#: QC2.1 RB29.1 RC25.2 RM6.2 UC8.4 UL1.19 UR1.23 UW1.16
PLT_RST_BUF#_R: CB10.2 RB29.2 RB30.2 UB1.13
PLUG_IN: JHP1.6 RA16.2
PLUG_IN_R: RA15.1 RA16.1 UA1.13
PMC_ACIN: CC14.1 DC1.2 RC26.2 UC4.D20
PMC_BATLOW#: RPC5.2 UC4.K26
PMC_CORE_PWROK: UB1.32 UC4.B7 UC9.2
PMC_PCIE_WAKE#: QC3.3 RPC5.1 UC4.F26
PMC_PLTRST#: QC2.3 RC48.1 UC4.F20 UC8.1 UC8.2
PMC_PLTRST#_R: RB30.1 RC48.2
PMC_SLP_S3#: UB1.106 UC4.D22
PMC_SLP_S4#: RB22.1 UC4.F22
PMON: PC217.2 PU1.9
PWR_LED#: C9.1 LED1.1 R12.1 UB1.92
RJ45_RX1+: JLAN1.3 TL1.15
RJ45_RX1-: JLAN1.6 TL1.16
RJ45_TX0+: JLAN1.1 TL1.9
RJ45_TX0-: JLAN1.2 TL1.10
RTC_RST#: CC25.1 CLRP2.1 RC49.2 RC54.2 RC83.1 UC4.C12
RTC_TEST#: CC24.1 CLRP1.1 RC47.2 RC54.1 RC84.1 UC4.C11
SATA_PRX_C_DTX_N0: CO7.2 JHDD1.5
SATA_PRX_C_DTX_N1: CO6.2 JODD1.5
SATA_PRX_C_DTX_P0: CO1.2 JHDD1.6
SATA_PRX_C_DTX_P1: CO8.2 JODD1.6
SATA_PRX_DTX_N0: CO7.1 UC4.AV16
SATA_PRX_DTX_N1: CO6.1 UC4.BA16
SATA_PRX_DTX_P0: CO1.1 UC4.AU16
SATA_PRX_DTX_P1: CO8.1 UC4.AY16
SATA_PTX_C_DRX_N0: CO3.2 JHDD1.3
SATA_PTX_C_DRX_N1: CO5.2 JODD1.3
SATA_PTX_C_DRX_P0: CO2.2 JHDD1.2
SATA_PTX_C_DRX_P1: CO4.2 JODD1.2
SATA_PTX_DRX_N0: CO3.1 UC4.BG7
SATA_PTX_DRX_N1: CO5.1 UC4.BF10
SATA_PTX_DRX_P0: CO2.1 UC4.BF6
SATA_PTX_DRX_P1: CO4.1 UC4.BD10
SATA_RCOMPN: RC16.1 UC4.AT18
SATA_RCOMPP: RC16.2 UC4.AU18
SD_CD#: JSD1.10 UR1.21
SD_CLK: CR9.1 JSD1.5 RR4.1
SD_CLK_R: RR4.2 UR1.14
SD_CMD: JSD1.2 RR5.2
SD_CMD_R: RR5.1 UR1.16
SD_D0: JSD1.7 RR3.2
SD_D0_R: RR3.1 UR1.13
SD_D1: JSD1.8 RR2.2
SD_D1_R: RR2.1 UR1.12
SD_D2: JSD1.9 RR7.2
SD_D2_R: RR7.1 UR1.18
SD_D3: JSD1.1 RR6.2
SD_D3_R: RR6.1 UR1.17
SD_GPIO1: RR8.1 UR1.19
SD_WP: JSD1.11 UR1.20
SKU_STRAP1: RC34.2 RC81.1 UC4.AV34
SKU_STRAP2: RC29.1 RC33.2 UC4.BA34
SKU_STRAP3: RC28.1 RC32.2 UC4.AY34
SOC_ENBKL: RC10.2 UB1.97
SOC_ENVDD: RC13.2 UB1.121
SOC_I2C0_CLK: T17.1(TP-1) UC4.BG28
SOC_I2C0_DATA: T16.1(TP-1) UC4.BH28
SOC_PCIE_WAKE#: QC3.1 RC27.1 RM3.1
SOC_SPI_CLK: RPC7.5 UC4.C22
SOC_SPI_CS0#: RPC7.8 UC4.C23
SOC_SPI_MISO: RPC7.7 UC4.B22
SOC_SPI_MOSI: RPC7.6 UC4.A21
SPI_CLK: RC53.1 RPC7.4 RPC8.4 UC10.6
SPI_CS0#: RC50.2 RPC7.1 RPC8.1 UC10.1
SPI_HOLD#: RC51.2 UC10.7
SPI_MISO: RPC7.2 RPC8.2 UC10.2
SPI_MOSI: RPC7.3 RPC8.3 UC10.5
SPI_WP#: RC52.2 UC10.3
SPK_L1-: LA1.1 UA1.43
SPK_L1-_CONN: CA29.1 DA4.3 JSPK1.1 LA1.2
SPK_L2+: LA2.1 UA1.42
SPK_L2+_CONN: CA28.1 DA4.2 JSPK1.2 LA2.2
SRN: PC221.1 PC222.1 PR221.3 PR227.2
SRP: PC221.2 PC223.1 PR221.2 PR226.2
SUSP: Q2.1 Q3.2 Q4.2 Q5.2 RQ5.1
SUSP#: PR411.1 Q2.2 RQ1.2 RQ2.1 RQ3.2 RQ4.2 RQ8.1 UB1.116
SYSON: PR410.1 UB1.95
TCM_LPC_CLK: RW2.1 UW1.21
TCM_SERIRQ: RB1.1 RW7.2 UW1.27 UW2.4
TON_DDR: PR408.2 PU303.9
TP2_CORE_VCC_S0IX: T20.1(TP-1) UC4.AA22
TP_CLK: C3.1 D1.3 JTP1.3 RB8.1 RB14.1 UB1.87
TP_CORE_V1P05_S4: T21.1(TP-1) UC4.AF30
TP_DATA: C4.1 D1.2 JTP1.2 RB9.1 RB15.1 UB1.88
TP_L: C6.1 JTP1.6 SW3.1 SW3.2
TP_R: C5.1 JTP1.5 SW4.1 SW4.2
TP_VCC: C1.1 JTP1.1 R1.2 R2.2
U3RXDN0: DS1.1 DS1.9 JUSB1.5 LS2.3 RS9.1
U3RXDP0: DS1.2 DS1.8 JUSB1.6 LS2.2 RS8.1
U3TXDN0: DS1.4 DS1.7 JUSB1.8 LS1.3 RS7.1
U3TXDP0: DS1.5 DS1.6 JUSB1.9 LS1.2 RS6.1
UG_DDR: PQ401.4 PU303.17
UGATE1: PQ702.1 PR728.1
UGATE1-1: PR728.2 PU602.17
UGATEG1: PQ701.1 PR708.1
UGATEG1-1: PR708.2 PU602.25
USB3_REXT0: RC55.1 UC4.M12
USB20_BT_N: RM17.2 RS19.1
USB20_BT_P: RM16.2 RS18.1
USB20_BT_R_N: JWLAN1.36 RM14.1 RM17.1
USB20_BT_R_P: JWLAN1.38 RM15.1 RM16.1
USB20_N0: LS3.4 RS3.2 UC4.K16
USB20_N0_L: DS2.6 JUSB1.2 LS3.3 RS3.1
USB20_N1: LS4.4 RS5.2 UC4.G14
USB20_N1_L: DS3.6 JUSB2.2 LS4.3 RS5.1
USB20_N2: LX1.4 RX13.1 UC4.J12
USB20_N2_R: JEDP1.2 LX1.3 RX13.2
USB20_N3: RS17.1 RS19.2 UC4.H10
USB20_P0: LS3.1 RS1.2 UC4.M16
USB20_P0_L: DS2.4 JUSB1.3 LS3.2 RS1.1
USB20_P1: LS4.1 RS4.2 UC4.J14
USB20_P1_L: DS3.4 JUSB2.3 LS4.2 RS4.1
USB20_P2: LX1.1 RX12.1 UC4.K12
USB20_P2_R: JEDP1.4 LX1.2 RX12.2
USB20_P3: RS16.1 RS18.2 UC4.K10
USB20_R_N3: RS17.2 US2.14
USB20_R_P3: RS16.2 US2.15
USB_EN#: UB1.84 US1.4 US3.4
USB_HUB_BT_N3: RM14.2 US2.7
USB_HUB_BT_P3: RM15.2 US2.8
USB_HUB_N1: JSB1.4 US2.11
USB_HUB_P1: JSB1.3 US2.12
USB_OC0#: RC59.2 RS2.2 RS20.2 UC4.C20
USB_OC1#: RC61.2 UC4.B20
USB_PLL_MON: RC62.2 UC4.M13
USB_RCOMP: RC60.2 UC4.C7 UC4.D6
VCIN0_PH1: PH100.1 PR110.2 RB20.1 UB1.109
VCIN1_AC_IN: DC1.1 PR228.2 PR229.1 PU1.5 UB1.110
VCIN1_ADP_PROCHOT: PR111.2 PR112.1 PR113.2 RB21.1 UB1.102
VCIN1_BATT_DROP: PC327.1 PR312.2 PR313.1 UB1.64
VCIN1_BATT_TEMP: PR109.2 PU1.15 UB1.63
VCORE_GSNS: PC709.2 PC763.2 PU602.12 PU602.30 RC73.1 UC4.N28
VCORE_VSNS: PC756.1 PC762.2 PR740.1 RC72.2 UC4.P28
VCOUT0_MAIN_PWR_ON: PR307.1 UB1.104
VCOUT1_PROCHOT#: PR111.1 PR224.1 RB24.1 UB1.103
VGA_CLKREQ#: RPC3.3 UC4.BG3
VGA_V1P35_S3_F1: CC39.1 RC70.1 UC4.BD1
VGATE: PR729.1 PU602.15 UB1.21
VGFX_VSNS: PC705.1 PR701.2 PR703.2 RC71.2 UC4.BB8
VL: PC325.1 PU302.7 R6.2 R13.2
VMB: PC104.1 PF101.2 PL102.1 PL103.1
VMB2: JBATT1.1 JBATT1.2 PF101.1
VR_HOT#: PC744.1 PR724.1 PU602.6 RB26.1
VR_ON: PR717.1 UB1.108
VR_SVID_ALERT#: PU602.4 RC39.2 RC40.2
VR_SVID_ALERT#_SOC: RC40.1 UC4.B24
VR_SVID_CLK: PR720.1 PR726.1 UC4.C25
VR_SVID_CLK_R: PR720.2 PU602.3
VR_SVID_DATA: PR721.1 PR725.1 RC41.2
VR_SVID_DATA_R: PR721.2 PU602.5
VR_SVID_DATA_SOC: RC41.1 UC4.A25
VSUM+: PC758.1 PC759.1 PR734.1 PR735.2 PR739.1 PU602.10
VSUM-: PC758.2 PC759.2 PC761.2 PH701.2 PL703.3 PR738.2 PR739.2
VSUMG+: PC726.2 PC727.2 PR710.2 PR711.2 PR714.2 PU602.32
VSUMG-: PC726.1 PC727.1 PH702.1 PL702.3 PR704.2 PR706.1 PR711.1
VTTREF_DDR: PC415.1 PU303.4
WAKE#_R: JWLAN1.1 RM2.2 RM3.2
WL_RST#: JWLAN1.22 RM6.1
WLAN_BT_OFF#: JWLAN1.5 QM1.3 RM18.1 RM21.1
WLAN_CLKREQ#: RM4.1 RPC3.2 UC4.BE3
WLAN_CLKREQ#_R: JWLAN1.7 RM4.2
XDP_H_PRDY#: RC38.2 UC4.D18
XDP_H_PREQ_BUF#: RC45.2 UC4.F16
XDP_H_TCK: RPC6.7 UC4.D14
XDP_H_TDI: RPC6.5 UC4.F12
XDP_H_TDO: RC46.2 UC4.G16
XDP_H_TMS: RPC6.6 UC4.F14
XDP_H_TRST#: RPC6.8 UC4.G12
XDP_OBSDATA_A0: T10.1(TP-1) UC4.N24
XDP_OBSDATA_A1: T11.1(TP-1) UC4.M20
XDP_OBSDATA_A2: T12.1(TP-1) UC4.J18
XDP_OBSDATA_A3: T13.1(TP-1) UC4.M18
XDP_RSTBTN#: CC15.1 T7.1(TP-1) UC4.BG9
XTAL_25M_IN: CC12.1 RC24.1 UC4.AH12 YC1.1
XTAL_25M_OUT: CC13.1 RC24.2 UC4.AH10 YC1.3
XTLI: CL16.2 UL1.29 YL1.3
XTLO: CL13.2 UL1.28 YL1.1
N10380: PQ200.2 PR200.2 PR201.1
N16597291: PC304.1 PR304.2
N16598283: PC318.1 PR310.2
N16598457: PC302.2 PR302.1
N16598563: PC317.2 PR309.1
N16600766: PC408.2 PR405.2 PU303.12
N16601416: PC417.1 PR403.2
N16602606: PC502.1 PJ502.2 PU501.3
N16602704: PC508.1 PR504.2
N16603012: PR502.2 PU501.2
N16605295: PC602.1 PJ601.2 PU601.5 PU601.9
N16605323: PC604.2 PR603.2 PR605.1 PU601.2
N16605357: PR602.2 PU601.7
N16605441: PC603.1 PR601.2 PR604.1 PU601.8
N16615810: PR722.2 PU602.8
N16616404: PC725.2 PR709.1
N16616872: PC751.2 PR730.1
N16617014: PC716.1 PR704.1
N16617018: PC716.2 PR706.2 PU602.31
N16617032: PC761.1 PR737.2
N16617036: PR737.1 PR738.1 PU602.11
N16617104: PC713.1 PR702.1 PR707.1 PU602.28
N16617138: PR717.2 PU602.2
N16617166: PC750.1 PR122.2 PR123.2 PR724.2 PR725.2 PR726.2
N16617198: PC713.2 PC714.1 PC719.2 PR703.1 PR705.1 PU602.29
N16617206: PC757.2 PC760.2 PR732.2 PU602.14
N16617222: PC757.1 PR733.2 PR736.2 PR740.2 PR741.1 PU602.13
N16617226: PC719.1 PR702.2
N16617230: PC738.1 PR719.2 PU602.21
N16617308: PR712.2 PU602.27
N16617390: PC760.1 PR741.2
N16617462: PC756.2 PR736.1
N16617530: PH702.2 PR710.1
N16617586: PC752.2 PR733.1
N16617598: PC714.2 PR701.1
N16617710: PC733.2 PR718.1 PU602.22
N16617722: PH701.1 PR734.2
N16617766: PC724.1 PR705.2
N16617930: PC755.1 PR731.2
N16618186: PC731.1 PR713.2
N16618510: PL702.2 PR714.1
N16618534: PL703.2 PR735.1
N17087503: RR1.2 UR1.8
N17458820: LED3.1 R12.2 R15.2
N17500377: CQ2.2 UQ1.12
N17500401: CQ6.2 UQ1.10
N17500568: CQ10.2 UQ2.12
N17500584: CQ14.2 UQ2.10
N18372963: RL6.2 UL1.31
N18373572: TPL1.1(TP-1) UL1.25
N18373578: TPL2.1(TP-1) UL1.27
N18442348: RB25.2 UB1.118
N18492193: CC31.1 L1.1
N18492196: CC32.1 L2.1
N18535411: CL14.1 RL8.2
N18535413: DL1.2 RL8.1 TL1.11 TL1.14
N18977277: CX13.1 QX2.2 RX11.2
N19132918: RC8.1 UC5.4
N19342204: RC12.1 UC6.4
N19670814: JBATT1.5 PR105.1 PR107.1 PR109.1
N19670901: PD100.3 PR116.1
N19732471: RC74.2 UC4.BJ6
N19773650: RW3.2 RW4.2 RW6.1 RW7.1
N19773695: RW6.2 RW9.1 UW2.6
N19773710: RW8.2 RW9.2 UW2.5
N19796007: CL15.1 TL1.3 TL1.6
N19801797: RS2.1 US1.3
N19854769: JWLAN1.20 RM5.1
N19857635: JWLAN1.49 RM11.2
N19992411: JDIMM1.197 RD5.2
N19992423: JDIMM1.201 RD6.2
N20191994: JWLAN1.51 RM12.2 RM21.2
N20264849: RS11.1 US2.13
N20529644: RS20.1 US3.3
N20531465: QM1.5 QM1.6 RM20.1
N20897061: LED2.2 R7.1
N20897066: LED3.2 R13.1
N20897117: LED4.2 R14.1
N20897124: LED1.2 R6.1
N21018227: JODD1.11 T22.1(TP-1)
N23009332: RA12.2 UA1.47
N23009443: CA10.1 RA11.2
N23009457: CA30.2 CA32.2 RA30.1 RA31.1
N23009590: CA31.1 RA30.2
N23009788: CA20.1 UA1.28
N23009828: CA21.1 UA1.19
N23009845: CA15.2 UA1.37
N23009849: CA15.1 UA1.35
N24385312: PR224.2 PU1.10
N24385422: PC214.1 PR220.2
N24385504: PC202.1 PQ200.3 PQ201.1 PQ201.2 PQ201.3 PQ202.1 PQ202.2 PQ202.3 PR201.2 PR211.1
N24385542: PC203.1 PC204.1 PC205.1 PC206.1 PL200.2 PQ204.5
N24385544: PR222.1 PR225.1 PU1.21
N24385582: PR226.1 PU1.20
N24385584: PR227.1 PU1.19
N24385612: PC211.2 PR214.2 PU1.28
N24385618: PC212.1 PR215.2 PR216.1 PU1.6
N24385720: PC201.1 PQ203.4 PR212.1
N24386383: PC200.2 PC202.2 PQ200.1 PQ202.4 PR209.1 PR210.2
N24386409: PD1.1 PR214.1
N24386941: PQ204.4 PR217.2
N24595306: PQ201.4 PR210.1
N28204186: PC219.1 PR223.2
N100842872: CC26.2 RC53.2
N102723193: T6.1(TP-1) UC4.BG18
N102723222: T5.1(TP-1) UC4.BH18
N102723231: T4.1(TP-1) UC4.BG21
N103320637: T9.1(TP-1) UC4.C21

Pads without a net: D3 2; D4 3; DL2 5; DS2 1 3; DS3 1 3; DY1 5 6; FD1 1; FD2 1; FD3 1; FD4 1; JBATT1 6; JDCIN1 5; JDIMM1 77 122 125 198; JEDP1 3 22 24 25 27 29; JHDD1 18 20 21 22; JHDMI1 13 14; JHP1 3; JKB1 25 26 27 28 29 30; JKB2 27 28 29 30; JLAN1 4 5 7 8; JP1 5 6; JPWRB1 3; JWLAN1 3 6 8 10 12 14 16 17 19 28 30 32 42 44 45 46 47 48 53 54; PU1 13 14 16; PU302 2; PU501 5; PU602 9 20; RPC1 1 8; RPC2 4 5; RPC9 1 8; TL1 4 5 12 13; UA1 2 3 4 14 15 16 44 45 48; UB1 1 6 14 16 17 18 25 26 27 28 29 36 38 66 70 71 73 75 76 85 89 98 101 107 127; UC4 A13 A17 AB2 AB3 AB7 AB9 AB12 AB13 AB14 AC1 AC3 AD2 AD3 AD4 AD6 AD9 AD10 AD12 AD40 AD41 AF4 AF6 AF13 AF14 AF40 AF41 AF48 AF50 AF51 AF52 AG51 AG53 AH13 AH14 AH40 AH44 AH52 AJ51 AK7 AK9 AK40 AK42 AK45 AK47 AK48 AK50 AK51 AK52 AL1 AL3 AL51 AL53 AM9 AM10 AM13 AM14 AM41 AM42 AM45 AM47 AM48 AM50 AM52 AP41 AP42 AP44 AP45 AP47 AP48 AP50 AP51 AP52 AR51 AR53 AT13 AT14 AT20 AT22 AT26 AT28 AT32 AT34 AT36 AT40 AT41 AT42 AT44 AT45 AT48 AT50 AT51 AU20 AU22 AU26 AU28 AU32 AU34 AU36 AU53 AV9 AV10 AV20 AV22 AV26 AV28 AV32 AV36 AV40 AV44 AV45 AV48 AV50 AV52 AW1 AW41 AW51 AW53 AY2 AY3 AY6 AY7 AY12 AY18 AY20 AY24 AY26 AY28 AY30 AY38 AY40 AY42 AY44 AY45 AY47 AY48 AY51 AY52 B4 B5 B12 B14 B16 B26 B28 BA1 BA3 BA18 BA20 BA24 BA26 BA28 BA36 BA38 BA42 BA51 BB3 BB4 BB44 BB47 BB49 BB50 BB51 BC14 BC18 BC24 BC36 BC38 BC40 BC44 BC52 BC53 BD2 BD5 BD12 BD16 BD18 BD20 BD22 BD26 BD28 BD32 BD34 BD36 BD38 BD40 BD42 BD44 BD47 BE46 BE51 BE52 BF2 BF14 BF22 BF26 BF27 BF28 BF32 BF34 BF40 BF42 BF48 BF50 BF52 BG23 BG24 BG25 BG26 BG27 BG29 BG32 BG33 BG35 BG36 BG37 BG38 BG40 BG41 BG43 BG47 BH4 BH5 BH6 BH7 BH8 BH22 BH24 BH26 BH32 BH34 BH36 BH38 BH40 BH42 BH44 BH46 BH47 BH48 BH49 BH50 BJ9 BJ25 BJ29 BJ33 BJ37 BJ41 BJ45 C13 C15 C16 C18 C19 C27 C30 D2 D26 D28 D32 D34 D48 E2 E46 F1 F18 F28 F32 F34 G2 G18 G24 G30 H3 H4 H5 H7 H8 J3 J28 J34 K3 K18 K20 K24 K28 K34 L1 L3 M2 M3 M4 M6 M7 M9 M10 M22 M24 M32 N3 N32 N34 P2 P3 P6 P7 P10 P12 P14 P34 R1 R3 T2 T3 T4 T6 T7 T9 T10 T12 T13 T14 V2 V3 V4 V6 V9 V10 V13 V14 W1 W3 Y2 Y3 Y4 Y6 Y12 Y13; UC5 1; UC6 1; UC7 1; UC9 1; UL1 6 7 9 10; UR1 22; US2 2 5 6 9 10 21 22 23 24; UW1 1 2 3 5 6 8 9 12 13 14; UX1 3; YS1 2 4

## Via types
v1: diameter 0.305, hole 0.152, TOP to BOTTOM, 44 vias
v2: diameter 0.406, hole 0.203, TOP to BOTTOM, 451 vias
v3: diameter 0.457, hole 0.203, TOP to BOTTOM, 2964 vias
v4: diameter 0.508, hole 0.254, TOP to BOTTOM, 35 vias

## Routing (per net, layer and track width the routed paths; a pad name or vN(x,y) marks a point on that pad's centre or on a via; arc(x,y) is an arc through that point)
1.05VS_GATE: length 7.1
  TOP w0.508: Q5.1 157.91,48.04 v2(157.16,48.04) 156.55,48.04 RQ9.1 CQ20.1 155.13,48.6 155.86,49.33 UQ3.4
1.8VS_ON: length 3.5
  TOP w0.203: 50.24,68.31 50.67,67.88 UQ2.3
  TOP w0.508: CQ12.2 49.15,68.79 RQ3.1 49.5,67.79 50.02,68.31 v2(50.15,68.31) 50.24,68.31
1.35VS_ON: length 4.1
  TOP w0.203: UQ2.5 50.8,67.08 50.55,66.83 50.3,66.83
  TOP w0.508: 49.23,66.83 49.23,66.83 49.17,66.77 v2(49.17,65.85) 49.17,64.92 RQ4.1 ; 49.23,66.83 CQ15.2 ; 49.23,66.83 50.3,66.83
3V5V_EN: length 215.8
  TOP w0.254: v3(107.4,12.68) 107.65,12.94 107.65,24.7 v3(108.16,25.21)
  IN2 w0.254: v3(108.16,25.21) 106.53,23.58 96.79,23.58 95.73,24.64 93.43,24.64 91.85,26.22 89.93,26.22 86.17,22.46 80.58,22.46 80.1,21.98 78.12,21.98 76.77,20.63 75.2,20.63 74.89,20.32 74.89,19.47 74.29,18.87 74.29,18.27 73.2,17.18 71.77,17.18 71.26,17.69 69.93,17.69 69.18,16.93 66.82,16.93 66.1,16.21 64.17,16.21 49.92,30.47 49.92,42.17 v3(46.78,45.3) ; v3(192.66,41) 192.66,40.49 192.18,40.01 190.31,40.01 189.5,40.82 186.92,40.82 184.9,38.8 184.9,31.63 181.58,28.31 181.58,22.3 166.96,7.68 128.6,7.68 124.44,11.85 110.16,11.85 109.33,12.68 v3(107.4,12.68)
  BOTTOM w0.254: v3(46.78,45.3) 46.83,45.34 46.83,45.7 46.58,45.95 PU302.1 ; PR307.2 PR306.2 PR308.1 PC313.1 192.47,41.59 192.66,41.4 v3(192.66,41) 192.66,40.83 192.26,40.43 PU301.1
3V/5VALW_PG: length 234.5
  TOP w0.203: UB1.15 v3(72.53,29.03)
  TOP w0.254: v3(104.3,29.85) 104.7,29.44 104.7,14.39 v3(105.67,13.42) ; v3(55.86,79.58) 56.32,80.04 62.64,80.04 64.02,81.42 PR601.1 ; PR501.2 v3(57.5,60.78) ; PR314.2 191.96,40.55 v3(191.96,41.02)
  IN2 w0.254: v3(105.67,13.42) 105.67,13.4 106.21,12.86 106.69,12.86 107.03,13.2 109.44,13.2 110.39,12.25 124.8,12.25 128.99,8.06 166.75,8.06 181.2,22.51 181.2,28.47 184.52,31.79 184.52,38.96 186.77,41.2 189.75,41.2 190.56,40.39 191.52,40.39 191.96,40.83 v3(191.96,41.02) ; v3(57.5,60.78) 57.5,60.43 62.29,55.64 62.29,45.82 63.7,44.42 63.7,41.85 64.33,41.22 64.33,36.53 69.75,31.1 70.46,31.1 v3(72.53,29.03) 73.23,28.33 75.51,28.33 76.12,28.93 87.19,28.93 88.41,30.15 90.25,30.15 91.77,31.68 103.13,31.68 104.3,30.51 v3(104.3,29.85)
  BOTTOM w0.254: v3(191.96,41.02) 191.81,40.87 PU301.2 ; v3(55.86,79.58) 55.86,78.62 56.53,77.96 56.53,77.3 57.31,76.51 57.31,71.28 56.39,70.37 56.39,65.95 57.11,65.24 57.11,61.86 57.5,61.46 v3(57.5,60.78)
3V_FB: length 2.5
  TOP w0.102: v3(191.36,41.26) v2(191.36,41.94)
  BOTTOM w0.254: PU301.3 v3(191.36,41.26) 191.36,41.74 PC302.1
3V_SN:
  vias: v2(193.5,32.41)
3V_VIN:
  vias: v2(188.09,34.35)
3VS_ON: length 3.5
  TOP w0.203: UQ1.3 190.05,25
  TOP w0.254: RQ1.1 CQ4.1 v2(190.74,24.58) 190.47,24.58 190.05,25
5V_FB: length 2.5
  BOTTOM w0.254: PC317.1 47.85,45.56 v2(47.31,46.1) 47.19,46.22 47.19,46.29 46.63,46.85 PU302.3
5V_SN:
  vias: v2(38.41,42.96)
5V_VIN:
  vias: v2(40.03,50.03)
5VS_ON: length 3.6
  TOP w0.203: UQ1.5 189.92,25.8 190.09,25.96 190.25,25.96 v2(190.71,26.42)
  TOP w0.254: v2(190.71,26.42) 190.89,26.61 CQ7.2 RQ2.2
+0.675VS: length 6.5
  TOP w0.508: CD16.1 130.16,37.89 CD17.1 130.16,39.66 v3(130.43,39.93) ; v3(130.62,45.14) 130.59,45.17 CD18.1
  BOTTOM w0.305: JDIMM1.204 v3(130.43,39.93)
  BOTTOM w0.356: v3(130.62,45.14) 130.49,45.14 130.13,45.5 JDIMM1.203
  vias: v3(151.07,39.76) v3(151.77,39.76)
+0.675VS_R: length 3.8
  TOP w0.102: RQ6.2 157.21,42.15 v2(157.23,42.17)
  TOP w0.508: RQ6.2 158.73,40.77 Q3.1
+0.675VSP: length 6.3
  TOP w0.102: v3(150.81,36.65) v2(150.81,37.36)
  IN2 w0.254: v3(150.81,36.65) 150.81,34.87 151.83,33.85 v3(153.35,33.85)
  BOTTOM w0.203: v3(153.35,33.85) 153.27,33.77 PU303.2
+1.05VALW: length 6.8
  TOP w0.381: v3(105.74,80.09) 106.38,80.73 CC51.2 ; v3(105.72,82.38) 105.52,82.58 CC55.2
  BOTTOM w0.254: v3(105.72,82.38) 106.1,82 UC4.V18 106.88,81.24 UC4.Y19 ; UC4.B6 98.5,87.89 v3(98.88,87.51) 99.01,87.63 UC4.C5 99.01,88.52 v3(98.98,88.55) 98.98,89.07 UC4.C3 ; UC4.U22 105.37,79.72 v3(105.74,80.09) 106.11,79.72 UC4.V22
  vias: v2(162.01,86.46) v3(57.16,77.53) v3(57.79,76.03) v3(57.79,75.4) v3(58.28,77.53) v3(58.38,76.06) v3(58.38,75.4) v3(58.99,76.06) v3(59.01,75.37) v3(59.57,76.13) v3(59.57,75.55) v3(98.27,92.6) v3(98.81,94.65) v3(98.86,92.53) v3(99.35,94.34) v3(136.91,98.28) v3(137.24,98.87) v3(137.5,98.28) v3(137.83,98.87) v3(138.08,98.31) v3(142.97,90.75) v3(143.42,90.31) v3(143.86,91.42) v3(143.86,89.86) v3(144.31,90.98) v3(162.94,85.26) v3(163.3,53.09) v3(163.3,52.35) v3(163.3,51.62) v3(163.41,84.84) v3(163.82,84.43) v3(164.24,53.17) v3(164.24,52.38) v3(164.19,51.57) v3(164.32,83.99) v3(164.76,83.56) v3(165.18,53.17) v3(165.16,52.33) v3(165.16,51.57)
+1.05VALWP: length 7.3
  TOP w0.254: PR505.1 PC503.1 57.37,60.15 55.56,61.96 55.56,64.47 56.39,65.31 PC505.1
  vias: v2(66.38,67.42)
+1.05VS: length 213.4
  TOP w0.254: v3(105.85,20.44) 105.85,25.08 v3(105.87,25.1) ; RB23.2 85.25,23.9 v3(85.3,23.96)
  TOP w0.305: CC58.1 105.64,79.42 v3(106.49,78.58) ; v3(106.52,82.38) 106.52,82.36 106.54,82.38 106.85,82.38 107.18,82.05 CC68.2
  TOP w0.356: v3(109.67,73.29) 109.72,73.24 CC59.2
  TOP w0.381: v3(111.99,73.28) 112.05,73.28 112.93,72.4 CC84.2 ; v3(106.53,79.31) 106.53,79.35 107.29,80.11 CC64.2 ; CC90.2 111.16,74.84 v3(111.21,74.79) ; CC77.2 112.14,73.9 v3(111.99,74.05) 111.99,74.7 CC63.2 ; v3(105.72,81.64) 105.32,81.64 105.08,81.88 CC85.2 ; CC62.2 118.37,75.24 118.37,74.91 v3(118.67,74.6)
  TOP w0.508: v3(127.24,90.4) 127.2,90.37 126.18,90.37 125.53,89.72 125.53,87.42 129.27,83.69 129.27,79.13 131.3,77.1 v3(131.3,69.15) ; v3(88.93,79.51) 89.31,79.51 90.63,80.83 92.31,80.83 94.33,78.81 v3(94.65,78.81) 94.65,80.02 93.43,81.24 93.43,83.27 94.46,84.29 95.65,84.29 96.27,84.92 v2(96.27,86.81) 96.27,87.46 95.4,88.33 v3(95.4,91.35)
  IN1 w0.508: v3(97.84,91.48) 97.7,91.35 v3(95.4,91.35)
  IN2 w0.254: v3(85.3,23.96) 87.05,23.96 89.7,26.6 92.01,26.6 93.59,25.02 96.13,25.02 96.41,24.75 105.52,24.75 v3(105.87,25.1)
  BOTTOM w0.254: v3(111.99,73.28) 112.37,73.66 112.38,73.66 ; v3(111.99,73.28) 112.37,72.9 UC4.AK36 ; v3(111.99,73.28) 111.99,73.28 UC4.AJ36 ; UC4.U19 105.34,81.26 v3(105.72,81.64) 105.69,81.64 UC4.U18 ; UC4.AN30 114.01,75.93 v3(114.43,76.36) 114.1,76.69 UC4.AN29 ; UC4.AA33 107.69,74.42 v3(107.29,74.81) ; v3(110.45,81.63) 110.41,81.63 UC4.AF18 UC4.AF16 ; UC4.AF21 UC4.AG21 v3(111.21,80.1) ; v3(105.85,20.44) 105.9,20.39 120.18,20.39 128.67,11.9 161.06,11.9 164.27,15.11 164.27,42.98 158.37,48.88 157.6,48.88 v3(154.52,51.96) ; 106.87,78.97 106.87,78.97 v3(106.49,78.58) 106.12,78.94 UC4.V24 ; 106.87,78.97 UC4.Y24 ; 106.87,78.97 v3(106.53,79.31) 106.9,79.69 UC4.Y22 ; v3(111.99,74.05) 112.38,73.66 ; 112.38,73.66 UC4.AK35 ; v3(106.52,82.38) 106.9,82 UC4.Y18 ; UC4.M14 103.28,83.78 103.64,83.42 v3(103.64,83.27) ; v3(114.36,77.81) 113.96,78.2 UC4.AN25
  BOTTOM w0.305: v3(94.65,78.81) 94.65,78.9 RC20.2
  BOTTOM w0.508: CC78.2 124.72,90.99 125.63,90.08 RC74.1 125.99,90.15 126.98,90.15 v3(127.24,90.4) ; RC39.1 87.9,78.86 88.55,79.51 v3(88.93,79.51) ; CC87.2 124.75,69.6 123.99,70.37 v3(123.73,70.37) ; CC88.2 126.4,72.73 v3(126.98,72.14)
  vias: v3(101.51,92.8) v3(105.74,74.81) v3(106.51,74.79) v3(107.3,73.29) v3(112.01,81.6) v3(112.05,80.88) v3(112.78,81.62) v3(112.83,80.86) v3(113.57,80.83) v3(115.16,76.4) v3(115.9,76.53) v3(116.67,79.31) v3(124.06,61.63) v3(124.7,61.65) v3(125.36,61.65) v3(148.09,52.05) v3(148.14,51.37) v3(148.85,51.41) v3(148.95,52.13) v3(149.51,51.41) v3(149.61,52.15) v3(150.25,51.34) v3(150.27,52.03)
+1.05VS_R: length 2.3
  TOP w0.102: v2(150.48,49.64) 151.46,48.66 Q4.1
+1.05VS_SOC: length 1.2
  BOTTOM w0.254: v3(107.3,75.56) 106.91,75.18 UC4.Y32 ; v3(108.03,75.54) 108.4,75.18 UC4.AC32
+1.05VSP_ON: length 5.3
  TOP w0.102: PR501.1 56.69,62.3 v2(56.55,62.44)
  TOP w0.254: PR501.1 PR503.1 PC501.1 59.67,62.69 60.66,62.69 60.94,62.41 PU501.7
